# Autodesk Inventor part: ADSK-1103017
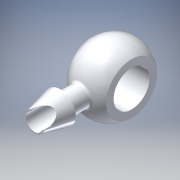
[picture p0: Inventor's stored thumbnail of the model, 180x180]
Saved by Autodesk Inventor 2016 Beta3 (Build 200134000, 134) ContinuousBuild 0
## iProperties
Shininess: 50.0
Length Units: 11272
Angle Units: 11279
Time Units: 11290
Mass Units: 11286
Length Display Precision: 4
Angle Display Precision: 2
Compacted: True
Created: 2000-09
Part Number: ADSK-1103017
Document SubType Name: Modeling
Description: AIR INTAKE
Mass: 0.433217 g
Surface Area: 3.22275 cm^2
Volume: 0.159859 cm^3
Density: 2.71 g/cm^3
Material: Aluminum-6061
Appearance: Aluminum - Flat
Density: 0.0
Volumn: 0.0
Area: 0.0
PropertySet Name: Model Information
Control State: 0
Master: False
Checked Out: False
Author: Autodesk, Inc.
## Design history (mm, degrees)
node "Revolution1" dims "d5" = 90 deg
  sketch "Sketch2"
    geometry: L1 (-0.521, -2.783)-(-5.347, -2.783); L2 (-5.347, -2.783)-(-5.347, 0.351); L3 (-0.521, -2.783)-(-0.521, 0.351); A1 r 3.429 centre (-2.934, -2.085) between (-0.521, 0.351) and (-5.347, 0.351); 1 further point
    constraints: 6 end point, 2 parallel, 2 point on circle, 1 centre point, 1 horizontal, 1 midpoint, 1 perpendicular, 1 vertical alignment
    dimensions: "d2" = 4.1275 dimension on A1 L1; "d3" = 4.826 distance of L1.start L1.end; "d4" = 3.429 radius of A1
workaxis "Work Axis1"
workplane "Work Plane1"
node "Extrusion4" dims "d17" = 0, "d18" = 6.35
  sketch "Sketch6"
    geometry: C1 r 1.27 at (1.587, 1.923); 1 further point
    constraints: 1 centre point, 1 coincident
    dimensions: "d19" = 2.54 diameter of C1
node "Extrusion5" dims "d20" = -12 deg, "d21" = 3.175
  sketch "Sketch7"
    geometry: C1 r 1.27 at (0, 0) reference; C2 r 1.905 at (0, 0)
    constraints: 1 centre point, 1 coincident
    dimensions: "d22" = 3.81 diameter of C2
node "Extrusion6" dims "d23" = 0, "d24" = 10.795
  sketch "Sketch8"
    geometry: C1 r 1.23 at (0, 0) reference; C2 r 1.048 at (0, 0)
    constraints: 1 centre point, 1 coincident
    dimensions: "d25" = 2.0955 diameter of C2
node "Fillet2" dims "d26" = 0.381
node "Extrusion7" dims "d27" = 25.4, "d28" = 0
  sketch "Sketch9"
    geometry: C1 r 3.135 at (0, 0) reference; C2 r 2.212 at (0, 0)
    constraints: 1 centre point, 1 coincident
body "Solid1"
other parameters: "d6" = 90 deg
